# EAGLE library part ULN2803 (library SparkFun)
Darlington Driver ULN2803 Darlington array. 500mA max per channel, 8-channel package. Spark Fun Electronics SKU : IC-ULN2803A
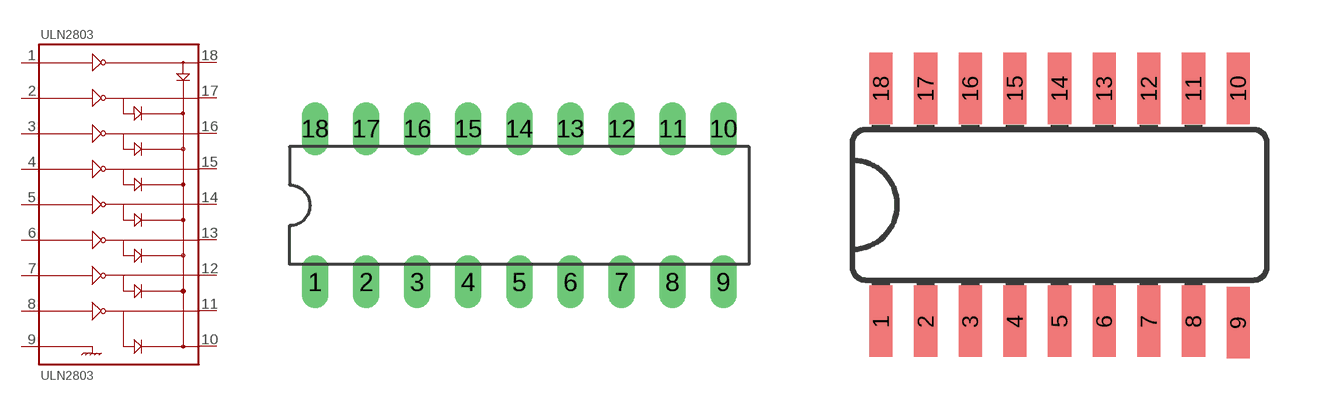
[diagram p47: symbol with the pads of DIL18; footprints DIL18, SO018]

Designator prefix ULN2803

## ULN2803DIP  [DIL18]
1  1
2  2
3  3
4  4
5  5
6  6
7  7
8  8
9  9
10  10
11  11
12  12
13  13
14  14
15  15
16  16
17  17
18  18

## ULN2803SOIC  [SO018]
Pads as for DIL18

## ULN2803SOICW  [SO18L]
Pads as for DIL18

## Footprint DIL18 (pad centres in mm)
Dual In Line Package
drill 0.813 long: 1 -10.16,-3.81; 2 -7.62,-3.81; 3 -5.08,-3.81; 4 -2.54,-3.81; 5 0,-3.81; 6 2.54,-3.81; 7 5.08,-3.81; 8 7.62,-3.81; 9 10.16,-3.81; 10 10.16,3.81; 11 7.62,3.81; 12 5.08,3.81; 13 2.54,3.81; 14 0,3.81; 15 -2.54,3.81; 16 -5.08,3.81; 17 -7.62,3.81; 18 -10.16,3.81

## Footprint SO018 (pad centres in mm)
smd 0.66 x 2.032: 1 -5.08,-3.315; 2 -3.81,-3.315; 3 -2.54,-3.315; 4 -1.27,-3.315; 5 0,-3.315; 6 1.27,-3.315; 7 2.54,-3.315; 8 3.81,-3.315; 9 5.08,-3.353; 10 5.08,3.315; 11 3.81,3.315; 12 2.54,3.315; 13 1.27,3.315; 14 0,3.315; 15 -1.27,3.315; 16 -2.54,3.315; 17 -3.81,3.315; 18 -5.08,3.315

## Footprint SO18L (pad centres in mm)
smd 0.66 x 2.032: 1 -0.635,-4.902; 2 0.635,-4.902; 3 1.905,-4.902; 4 3.175,-4.902; 5 4.445,-4.902; 6 5.715,-4.902; 7 6.985,-4.902; 8 8.255,-4.902; 9 9.525,-4.902; 10 9.525,4.902; 11 8.255,4.902; 12 6.985,4.902; 13 5.715,4.902; 14 4.445,4.902; 15 3.175,4.902; 16 1.905,4.902; 17 0.635,4.902; 18 -0.635,4.902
